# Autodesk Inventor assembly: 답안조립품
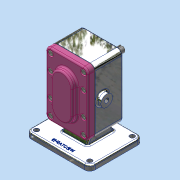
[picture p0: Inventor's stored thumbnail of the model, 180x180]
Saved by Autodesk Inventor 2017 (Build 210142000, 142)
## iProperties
Part Number: 답안조립품
Material: 일반
Document SubType Name: Assembly
Designer: MRC
Author: MRC
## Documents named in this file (11)
- C:\Users\MRC\Desktop\700407V1057\답안조립품.iam
- C:\Users\MRC\Desktop\700407V1057\본체.ipt
- C:\Users\MRC\Desktop\700407V1057\Ű 6 x 6 x 18.ipt
- C:\Users\MRC\Desktop\700407V1057\개스킷.ipt
- C:\Users\MRC\Desktop\700407V1057\메인축.ipt
- C:\Users\MRC\Desktop\700407V1057\베어링부시.ipt
- C:\Users\MRC\Desktop\700407V1057\볼트 M5.ipt
- C:\Users\MRC\Desktop\700407V1057\서브축.ipt
- C:\Users\MRC\Desktop\700407V1057\스퍼기어.ipt
- C:\Users\MRC\Desktop\700407V1057\오일 실 16 28 7.ipt
- C:\Users\MRC\Desktop\700407V1057\커버.ipt
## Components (3 placed, 2 different names)
1. Ű 6 x 6 x 18:1
2. 개스킷:1
3. Ű 6 x 6 x 18:2
